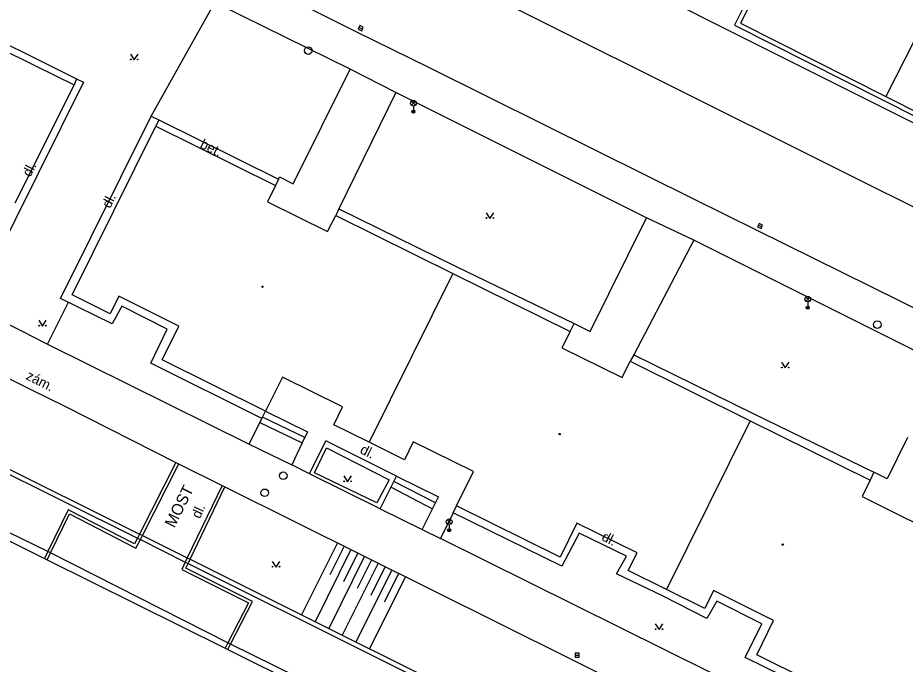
# Model space of a CAD drawing. Extents: x -602419 to -601554, y -1162937 to -1162362.
# Drawn here: x -602127.5 to -602069.2, y -1162500.8 to -1162458.3 of the extents above; entities that cross this region are included whole.
import ezdxf

# ---------------------------------------------------------------- set-up
doc = ezdxf.new("R2010")
doc.units = 0
doc.layers.add('Podklad', color=7, linetype='Continuous')

msp = doc.modelspace()

# ---------------------------------------------------------------- linework, layer by layer
at = {"layer": 'Podklad'}
for p, q in [((-602105.0641, -1162458.9189), (-602104.8359, -1162459.0209)), ((-602101.6225, -1162464.03), (-602101.3575, -1162463.765)), ((-602101.6225, -1162463.765), (-602101.3575, -1162464.03)), ((-602101.49, -1162464.085), (-602101.49, -1162464.46)), ((-602078.8341, -1162471.9191), (-602078.6057, -1162472.0207)), ((-602075.7225, -1162476.9), (-602075.4575, -1162476.635)), ((-602075.7225, -1162476.635), (-602075.4575, -1162476.9)), ((-602075.59, -1162476.955), (-602075.59, -1162477.33)), ((-602099.2725, -1162491.53), (-602099.0075, -1162491.265)), ((-602099.2725, -1162491.265), (-602099.0075, -1162491.53)), ((-602099.14, -1162491.585), (-602099.14, -1162491.96)), ((-602090.855, -1162500.17), (-602090.605, -1162500.17))]:
    msp.add_line(p, q, dxfattribs=at)
for points in [[(-602119.69, -1162445.21), (-602056.89, -1162476.59)], [(-602067.6599, -1162477.83), (-602078.96, -1162472.25), (-602083.03, -1162470.23), (-602092.86, -1162465.34), (-602100.43, -1162461.58), (-602105.24, -1162459.2), (-602114.08, -1162454.79), (-602118.63, -1162452.48), (-602121.19, -1162451.25)], [(-602110.36, -1162468.9), (-602110.29, -1162468.74), (-602109.38, -1162469.19), (-602105.64, -1162461.67), (-602119.79, -1162454.68), (-602121.69, -1162453.74)], [(-602118.7199, -1162464.75), (-602114.54, -1162457.2799), (-602114.5371, -1162457.2749), (-602113.3518, -1162455.1533)], [(-602089.04, -1162454.93), (-602080.77, -1162459.12), (-602054.62, -1162472.2199), (-602056.89, -1162476.59), (-602056.46, -1162476.78)], [(-602079.76, -1162457.5), (-602080.4099, -1162458.78), (-602053.93, -1162472.14)], [(-602079.34, -1162457.34), (-602080, -1162458.65), (-602053.79, -1162471.88)], [(-602131.45, -1162458.4099), (-602123.61, -1162462.3)], [(-602067.95, -1162458.51), (-602070.45, -1162463.4699)], [(-602131.28, -1162458.99), (-602126.27, -1162461.4699)], [(-602120.07, -1162460.675), (-602119.82, -1162461.05), (-602119.57, -1162460.675)], [(-602126.27, -1162461.4699), (-602123.78, -1162462.7)], [(-602102.65, -1162463.19), (-602105.64, -1162461.67)], [(-602123.61, -1162462.3), (-602123.1599, -1162462.52), (-602129.14, -1162474.51), (-602132.07, -1162473.02), (-602131.79, -1162472.53)], [(-602123.61, -1162462.3), (-602123.78, -1162462.7)], [(-602123.78, -1162462.7), (-602127.6599, -1162470.46)], [(-602102.65, -1162463.19), (-602106.39, -1162470.85)], [(-602086.17, -1162471.43), (-602102.65, -1162463.19)], [(-602111.44, -1162484.62), (-602118.74, -1162480.98), (-602117.67, -1162478.75), (-602120.63, -1162477.24), (-602121.28, -1162478.39), (-602124.67, -1162476.73), (-602118.7199, -1162464.75), (-602118.21, -1162465)], [(-602118.21, -1162465), (-602118.4099, -1162465.4099)], [(-602118.21, -1162465), (-602110.36, -1162468.9)], [(-602123.9099, -1162476.5), (-602118.4099, -1162465.4099)], [(-602118.4099, -1162465.4099), (-602110.54, -1162469.31)], [(-602110.36, -1162468.9), (-602110.54, -1162469.31)], [(-602110.54, -1162469.31), (-602111.07, -1162470.39)], [(-602111.07, -1162470.39), (-602107.13, -1162472.34)], [(-602106.39, -1162470.85), (-602106.59, -1162471.27)], [(-602106.39, -1162470.85), (-602098.68, -1162474.64), (-602090.94, -1162478.37)], [(-602107.13, -1162472.34), (-602106.59, -1162471.27)], [(-602106.59, -1162471.27), (-602098.9, -1162475.09)], [(-602096.71, -1162471.0949), (-602096.46, -1162471.4699), (-602096.21, -1162471.0949)], [(-602089.88, -1162478.9), (-602086.17, -1162471.43)], [(-602083.08, -1162472.9099), (-602086.17, -1162471.43)], [(-602068.1, -1162480.4), (-602083.08, -1162472.9099), (-602087.02, -1162480.43)], [(-602098.9, -1162475.09), (-602104.4, -1162486.17)], [(-602098.9, -1162475.09), (-602091.2, -1162478.9)], [(-602121.4099, -1162477.74), (-602123.9099, -1162476.5)], [(-602120.83, -1162476.57), (-602121.4099, -1162477.74)], [(-602116.89, -1162478.54), (-602120.83, -1162476.57)], [(-602125.52, -1162479.74), (-602124.1519, -1162476.9837)], [(-602126.09, -1162479.45), (-602128.83, -1162478.06)], [(-602126.1, -1162478.165), (-602125.85, -1162478.54), (-602125.6, -1162478.165)], [(-602118, -1162480.77), (-602116.89, -1162478.54)], [(-602091.2, -1162478.9), (-602090.94, -1162478.37)], [(-602090.94, -1162478.37), (-602089.88, -1162478.9)], [(-602091.2, -1162478.9), (-602091.73, -1162479.9699)], [(-602126.09, -1162479.45), (-602125.52, -1162479.74)], [(-602125.52, -1162479.74), (-602112.27, -1162486.3)], [(-602091.73, -1162479.9699), (-602087.78, -1162481.92)], [(-602111.2, -1162484.14), (-602118, -1162480.77)], [(-602087.78, -1162481.92), (-602087.25, -1162480.86)], [(-602087.02, -1162480.43), (-602087.25, -1162480.86)], [(-602087.25, -1162480.86), (-602079.36, -1162484.76)], [(-602087.02, -1162480.43), (-602079.14, -1162484.31), (-602071.24, -1162488.15)], [(-602077.32, -1162480.915), (-602077.07, -1162481.29), (-602076.82, -1162480.915)], [(-602129.38, -1162481.33), (-602126.57, -1162482.73)], [(-602110.09, -1162481.9099), (-602111.2, -1162484.14)], [(-602106.14, -1162483.85), (-602110.09, -1162481.9099)], [(-602139.55, -1162482.55), (-602119.61, -1162492.48)], [(-602139.42, -1162482.28), (-602119.48, -1162492.2199)], [(-602126.57, -1162482.73), (-602124.39, -1162483.81), (-602117.09, -1162487.5)], [(-602106.7199, -1162485.03), (-602106.14, -1162483.85)], [(-602111.44, -1162484.62), (-602111.2, -1162484.14)], [(-602111.2, -1162484.14), (-602108.44, -1162485.5)], [(-602112.27, -1162486.3), (-602111.44, -1162484.62)], [(-602111.57, -1162484.88), (-602108.79, -1162486.2199)], [(-602108.61, -1162485.86), (-602111.39, -1162484.52)], [(-602104.4, -1162486.17), (-602106.7199, -1162485.03)], [(-602079.36, -1162484.76), (-602084.87, -1162495.85)], [(-602079.36, -1162484.76), (-602071.48, -1162488.67)], [(-602108.44, -1162485.5), (-602108.79, -1162486.2199)], [(-602108.31, -1162488.25), (-602107.25, -1162486.09)], [(-602102.6, -1162488.4), (-602107.25, -1162486.09)], [(-602102.07, -1162487.33), (-602104.4, -1162486.17)], [(-602101.5, -1162486.1599), (-602102.07, -1162487.33)], [(-602097.55, -1162488.11), (-602101.5, -1162486.1599)], [(-602069.04, -1162485.87), (-602070.38, -1162488.58)], [(-602112.27, -1162486.3), (-602109.48, -1162487.67)], [(-602108.79, -1162486.2199), (-602109.48, -1162487.67)], [(-602103.08, -1162488.64), (-602103.88, -1162490.15), (-602107.98, -1162488.19), (-602107.19, -1162486.55), (-602103.08, -1162488.64)], [(-602117.09, -1162487.5), (-602119.48, -1162492.2199)], [(-602119.29, -1162492.31), (-602116.89, -1162487.6)], [(-602117.09, -1162487.5), (-602113.88, -1162489.1)], [(-602108.31, -1162488.25), (-602109.48, -1162487.67)], [(-602125.5, -1162493.36), (-602135.68, -1162488.4), (-602140.7199, -1162498.51), (-602140.83, -1162498.7199)], [(-602103.67, -1162490.56), (-602108.31, -1162488.25)], [(-602106.06, -1162488.395), (-602105.81, -1162488.77), (-602105.56, -1162488.395)], [(-602103.67, -1162490.56), (-602102.6, -1162488.4)], [(-602102.6, -1162488.4), (-602099.84, -1162489.77)], [(-602098.65, -1162490.35), (-602097.55, -1162488.11)], [(-602071.24, -1162488.15), (-602071.48, -1162488.67)], [(-602070.38, -1162488.58), (-602071.24, -1162488.15)], [(-602114.06, -1162489.01), (-602116.34, -1162493.78)], [(-602116.1599, -1162493.87), (-602113.88, -1162489.1)], [(-602113.88, -1162489.1), (-602073.08, -1162509.4099)], [(-602102.96, -1162489.12), (-602100.23, -1162490.55)], [(-602100.03, -1162490.1599), (-602102.78, -1162488.76)], [(-602071.48, -1162488.67), (-602072.01, -1162489.75)], [(-602100.23, -1162490.55), (-602099.84, -1162489.77)], [(-602072.01, -1162489.75), (-602069.88, -1162490.81)], [(-602119.61, -1162492.48), (-602119.8, -1162492.86), (-602124.17, -1162490.62), (-602125.5, -1162493.36)], [(-602103.67, -1162490.56), (-602100.9099, -1162491.92)], [(-602100.9099, -1162491.92), (-602100.23, -1162490.55)], [(-602098.88, -1162490.82), (-602099.7199, -1162492.51)], [(-602098.88, -1162490.82), (-602098.65, -1162490.35)], [(-602072.35, -1162503.94), (-602079.7, -1162500.33), (-602078.6, -1162498.12), (-602081.55, -1162496.61), (-602082.2199, -1162497.76), (-602085.09, -1162496.3), (-602088.1599, -1162494.82), (-602087.5, -1162493.6599), (-602090.6, -1162492.15), (-602091.74, -1162494.33), (-602098.88, -1162490.82)], [(-602091.86, -1162493.73), (-602098.65, -1162490.35)], [(-602069.88, -1162490.81), (-602068.06, -1162491.71)], [(-602125.32, -1162493.45), (-602124.08, -1162490.89), (-602119.71, -1162493.13), (-602119.42, -1162492.57)], [(-602100.9099, -1162491.92), (-602099.7199, -1162492.51)], [(-602090.75, -1162491.49), (-602091.86, -1162493.73)], [(-602086.8, -1162493.44), (-602090.75, -1162491.49)], [(-602128.2199, -1162492.57), (-602125.7199, -1162493.81)], [(-602119.48, -1162492.2199), (-602119.61, -1162492.48)], [(-602119.61, -1162492.48), (-602119.42, -1162492.57)], [(-602119.48, -1162492.2199), (-602119.4699, -1162492.2199)], [(-602119.4699, -1162492.2199), (-602119.29, -1162492.31)], [(-602119.42, -1162492.57), (-602119.29, -1162492.31)], [(-602119.42, -1162492.57), (-602116.4699, -1162494.05)], [(-602119.29, -1162492.31), (-602116.34, -1162493.78)], [(-602073.2, -1162505.6599), (-602099.7199, -1162492.51)], [(-602106.48, -1162492.78), (-602108.84, -1162497.52)], [(-602106.03, -1162493.01), (-602106.98, -1162494.9)], [(-602125.5, -1162493.36), (-602125.7199, -1162493.81)], [(-602125.54, -1162493.9), (-602125.32, -1162493.45)], [(-602125.32, -1162493.45), (-602125.5, -1162493.36)], [(-602113.67, -1162499.35), (-602125.32, -1162493.45)], [(-602116.34, -1162493.78), (-602116.4699, -1162494.05)], [(-602116.34, -1162493.78), (-602116.1599, -1162493.87)], [(-602105.59, -1162493.23), (-602107.95, -1162497.9699)], [(-602104.69, -1162493.67), (-602107.05, -1162498.4099)], [(-602105.14, -1162493.45), (-602106.08, -1162495.35)], [(-602087.38, -1162494.61), (-602086.8, -1162493.44)], [(-602125.7199, -1162493.81), (-602125.54, -1162493.9)], [(-602125.54, -1162493.9), (-602113.86, -1162499.71)], [(-602116.4699, -1162494.05), (-602116.7, -1162494.54), (-602112.32, -1162496.73), (-602113.67, -1162499.35)], [(-602116.4699, -1162494.05), (-602116.29, -1162494.14)], [(-602116.44, -1162494.45), (-602116.29, -1162494.14)], [(-602116.29, -1162494.14), (-602116.1599, -1162493.87)], [(-602116.29, -1162494.14), (-602116.28, -1162494.14)], [(-602116.28, -1162494.14), (-602092.4099, -1162506.06), (-602069.46, -1162517.46)], [(-602116.1599, -1162493.87), (-602116.15, -1162493.87)], [(-602116.15, -1162493.87), (-602092.27, -1162505.8), (-602069.33, -1162517.19)], [(-602110.76, -1162494.005), (-602110.51, -1162494.38), (-602110.26, -1162494.005)], [(-602103.8, -1162494.12), (-602106.1599, -1162498.86)], [(-602104.24, -1162493.9), (-602105.19, -1162495.79)], [(-602103.35, -1162494.34), (-602104.29, -1162496.24)], [(-602112.05, -1162496.64), (-602116.44, -1162494.45)], [(-602102.9, -1162494.56), (-602105.26, -1162499.31)], [(-602102.45, -1162494.79), (-602103.4, -1162496.69)], [(-602084.87, -1162495.85), (-602087.38, -1162494.61)], [(-602102.01, -1162495.01), (-602104.37, -1162499.76)], [(-602082.35, -1162497.1), (-602084.87, -1162495.85)], [(-602081.78, -1162495.93), (-602082.35, -1162497.1)], [(-602077.83, -1162497.9), (-602081.78, -1162495.93)], [(-602113.5, -1162499.44), (-602112.05, -1162496.64)], [(-602085.6, -1162498.115), (-602085.35, -1162498.49), (-602085.1, -1162498.115)], [(-602078.94, -1162500.14), (-602077.83, -1162497.9)], [(-602113.67, -1162499.35), (-602113.86, -1162499.71)], [(-602113.68, -1162499.8), (-602113.5, -1162499.44)], [(-602113.5, -1162499.44), (-602113.67, -1162499.35)], [(-602103.24, -1162504.51), (-602113.5, -1162499.44)], [(-602113.86, -1162499.71), (-602113.68, -1162499.8)], [(-602113.68, -1162499.8), (-602103.92, -1162504.65)], [(-602072.14, -1162503.51), (-602078.94, -1162500.14)]]:
    msp.add_lwpolyline(points, dxfattribs=at)
for points in [[(-602105.1151, -1162459.033), (-602104.8869, -1162459.135), (-602104.7849, -1162458.9068), (-602105.0131, -1162458.8048)], [(-602078.8849, -1162472.0333), (-602078.6565, -1162472.1349), (-602078.5549, -1162471.9065), (-602078.7833, -1162471.8049)], [(-602090.855, -1162500.295), (-602090.605, -1162500.295), (-602090.605, -1162500.045), (-602090.855, -1162500.045)]]:
    msp.add_lwpolyline(points, close=True, dxfattribs=at)
for centre, radius in [((-602108.4, -1162460.44), 0.25), ((-602120.0451, -1162461.0249), 0.025), ((-602119.5954, -1162461.0249), 0.025), ((-602101.49, -1162463.8975), 0.1875), ((-602101.49, -1162464.46), 0.1), ((-602101.49, -1162464.46), 0.0723), ((-602101.49, -1162464.46), 0.0438), ((-602096.6851, -1162471.4448), 0.025), ((-602096.2354, -1162471.4448), 0.025), ((-602111.4, -1162475.96), 0.045), ((-602111.4, -1162475.96), 0.0199), ((-602075.59, -1162476.7675), 0.1875), ((-602075.59, -1162477.33), 0.1), ((-602075.59, -1162477.33), 0.0723), ((-602075.59, -1162477.33), 0.0438), ((-602126.0751, -1162478.5149), 0.025), ((-602125.6254, -1162478.5149), 0.025), ((-602071.02, -1162478.45), 0.25), ((-602077.2951, -1162481.2649), 0.025), ((-602076.8454, -1162481.2649), 0.025), ((-602091.88, -1162485.64), 0.045), ((-602091.88, -1162485.64), 0.0199), ((-602110.04, -1162488.38), 0.25), ((-602106.0351, -1162488.7449), 0.025), ((-602105.5854, -1162488.7449), 0.025), ((-602111.25, -1162489.5), 0.25), ((-602099.14, -1162491.3975), 0.1875), ((-602099.14, -1162491.96), 0.1), ((-602099.14, -1162491.96), 0.0723), ((-602099.14, -1162491.96), 0.0438), ((-602077.23, -1162492.9), 0.045), ((-602077.23, -1162492.9), 0.0199), ((-602110.7351, -1162494.3549), 0.025), ((-602110.2854, -1162494.3549), 0.025), ((-602085.5751, -1162498.4649), 0.025), ((-602085.1254, -1162498.4649), 0.025)]:
    msp.add_circle(centre, radius, dxfattribs=at)

# ---------------------------------------------------------------- texts
for s, height, rotation, p in [('bet.', 0.65, 333.66, (-602115.56, -1162466.8)), ('dl.', 0.65, 63.49, (-602126.64, -1162468.79)), ('dl.', 0.65, 63.49, (-602121.4099, -1162470.85)), (' zám.', 0.65, 333.57, (-602127.21, -1162481.9099)), ('dl.', 0.65, 333.73, (-602105.05, -1162486.87)), ('MOST', 0.75, 63.56, (-602117.19, -1162491.85)), ('dl.', 0.65, 65.64, (-602115.51, -1162491.24)), ('dl.', 0.65, 333.04, (-602089.18, -1162492.59))]:
    msp.add_text(s, height=height, rotation=rotation, dxfattribs=at).set_placement(p)

doc.saveas('drawing.dxf')
